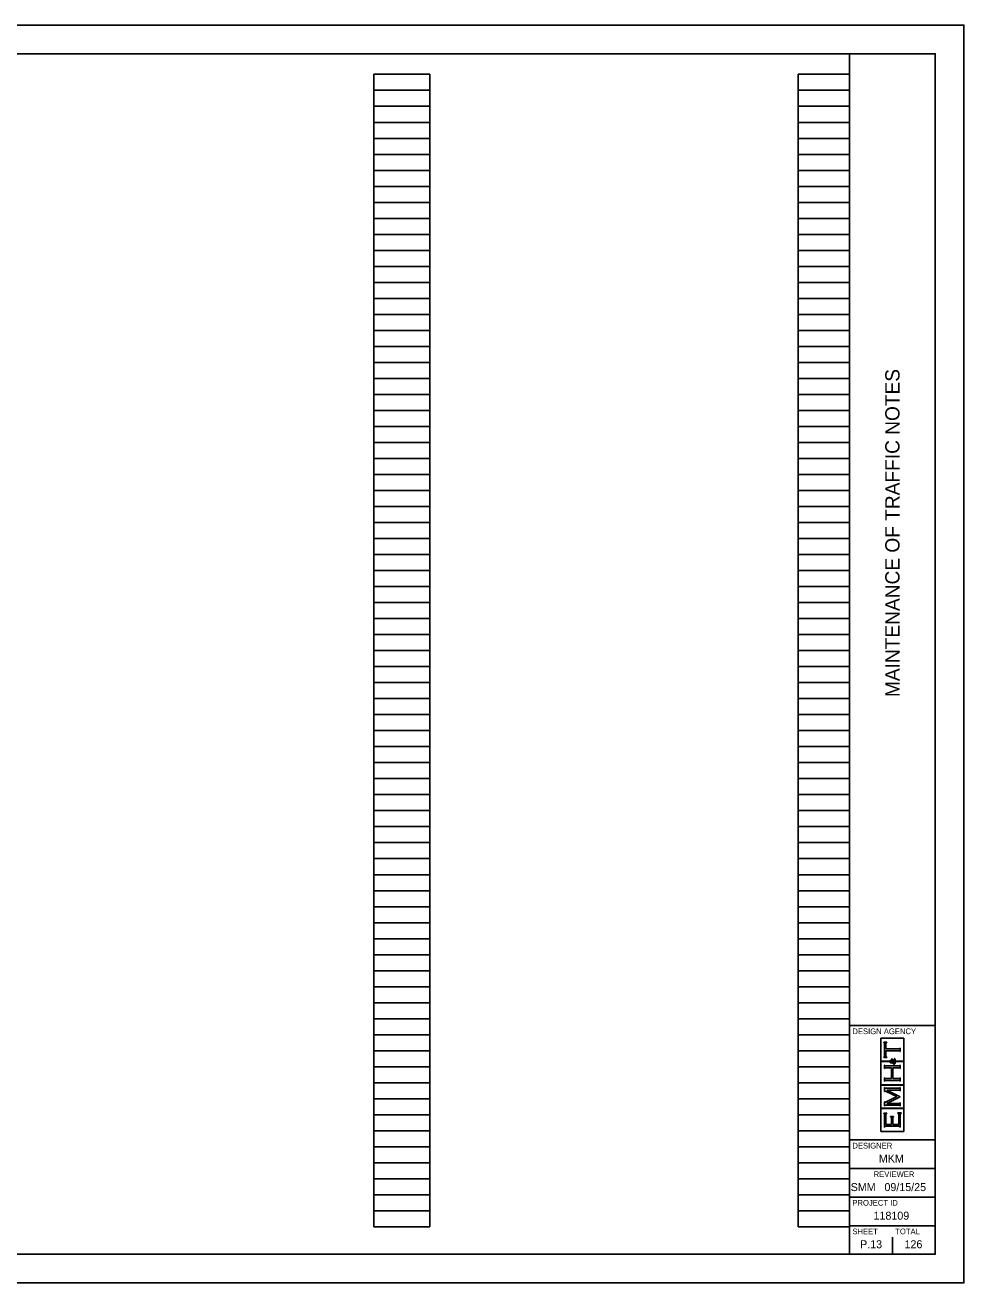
# Model space of a CAD drawing. Extents: x 0 to 34, y 0 to 22.
# Drawn here: x 17.58 to 34, y 0 to 22 of the extents above; entities that cross this region are included whole.
import ezdxf

# ---------------------------------------------------------------- set-up
doc = ezdxf.new("R2010")
doc.units = 0
for name, color, linetype in [('SH_Border', 7, 'Continuous'), ('SH_Cut_Line', 7, 'Continuous'), ('SH_Data', 7, 'Continuous')]:
    doc.layers.add(name, color=color, linetype=linetype)

msp = doc.modelspace()

# ---------------------------------------------------------------- linework, layer by layer
at = {"layer": 'SH_Border'}
for p, q in [((32, 0.5), (32, 21.5)), ((32, 4.5), (33.5, 4.5)), ((32, 2.5), (33.5, 2.5)), ((32, 2), (33.5, 2)), ((32, 1.5), (33.5, 1.5)), ((32, 1), (33.5, 1))]:
    msp.add_line(p, q, dxfattribs=at)
msp.add_lwpolyline([(1.5, 21.5), (33.5, 21.5), (33.5, 0.5), (1.5, 0.5)], close=True, dxfattribs=at)
at = {"layer": 'SH_Cut_Line'}
msp.add_lwpolyline([(0, 0), (34, 0), (34, 22), (0, 22)], close=True, dxfattribs=at)
at = {"layer": 'SH_Data'}
for p, q in [((23.68, 0.98), (23.68, 21.14)), ((23.68, 21.14), (24.66, 21.14)), ((24.66, 0.98), (24.66, 21.14)), ((31.1, 0.98), (31.1, 21.14)), ((31.1, 21.14), (32, 21.14)), ((32, 0.98), (32, 21.14)), ((23.68, 20.86), (24.66, 20.86)), ((31.1, 20.86), (32, 20.86)), ((23.68, 20.58), (24.66, 20.58)), ((31.1, 20.58), (32, 20.58)), ((23.68, 20.3), (24.66, 20.3)), ((31.1, 20.3), (32, 20.3)), ((23.68, 20.02), (24.66, 20.02)), ((31.1, 20.02), (32, 20.02)), ((23.68, 19.74), (24.66, 19.74)), ((31.1, 19.74), (32, 19.74)), ((23.68, 19.46), (24.66, 19.46)), ((31.1, 19.46), (32, 19.46)), ((23.68, 19.18), (24.66, 19.18)), ((31.1, 19.18), (32, 19.18)), ((23.68, 18.9), (24.66, 18.9)), ((31.1, 18.9), (32, 18.9)), ((23.68, 18.62), (24.66, 18.62)), ((31.1, 18.62), (32, 18.62)), ((23.68, 18.34), (24.66, 18.34)), ((31.1, 18.34), (32, 18.34)), ((23.68, 18.06), (24.66, 18.06)), ((31.1, 18.06), (32, 18.06)), ((23.68, 17.78), (24.66, 17.78)), ((31.1, 17.78), (32, 17.78)), ((23.68, 17.5), (24.66, 17.5)), ((31.1, 17.5), (32, 17.5)), ((23.68, 17.22), (24.66, 17.22)), ((31.1, 17.22), (32, 17.22)), ((23.68, 16.94), (24.66, 16.94)), ((31.1, 16.94), (32, 16.94)), ((23.68, 16.66), (24.66, 16.66)), ((31.1, 16.66), (32, 16.66)), ((23.68, 16.38), (24.66, 16.38)), ((31.1, 16.38), (32, 16.38)), ((23.68, 16.1), (24.66, 16.1)), ((31.1, 16.1), (32, 16.1)), ((23.68, 15.82), (24.66, 15.82)), ((31.1, 15.82), (32, 15.82)), ((23.68, 15.54), (24.66, 15.54)), ((31.1, 15.54), (32, 15.54)), ((23.68, 15.26), (24.66, 15.26)), ((31.1, 15.26), (32, 15.26)), ((23.68, 14.98), (24.66, 14.98)), ((31.1, 14.98), (32, 14.98)), ((23.68, 14.7), (24.66, 14.7)), ((31.1, 14.7), (32, 14.7)), ((23.68, 14.42), (24.66, 14.42)), ((31.1, 14.42), (32, 14.42)), ((23.68, 14.14), (24.66, 14.14)), ((31.1, 14.14), (32, 14.14)), ((23.68, 13.86), (24.66, 13.86)), ((31.1, 13.86), (32, 13.86)), ((23.68, 13.58), (24.66, 13.58)), ((31.1, 13.58), (32, 13.58)), ((23.68, 13.3), (24.66, 13.3)), ((31.1, 13.3), (32, 13.3)), ((23.68, 13.02), (24.66, 13.02)), ((31.1, 13.02), (32, 13.02)), ((23.68, 12.74), (24.66, 12.74)), ((31.1, 12.74), (32, 12.74)), ((23.68, 12.46), (24.66, 12.46)), ((31.1, 12.46), (32, 12.46)), ((23.68, 12.18), (24.66, 12.18)), ((31.1, 12.18), (32, 12.18)), ((23.68, 11.9), (24.66, 11.9)), ((31.1, 11.9), (32, 11.9)), ((23.68, 11.62), (24.66, 11.62)), ((31.1, 11.62), (32, 11.62)), ((23.68, 11.34), (24.66, 11.34)), ((31.1, 11.34), (32, 11.34)), ((23.68, 11.06), (24.66, 11.06)), ((31.1, 11.06), (32, 11.06)), ((23.68, 10.78), (24.66, 10.78)), ((31.1, 10.78), (32, 10.78)), ((23.68, 10.5), (24.66, 10.5)), ((31.1, 10.5), (32, 10.5)), ((23.68, 10.22), (24.66, 10.22)), ((31.1, 10.22), (32, 10.22)), ((23.68, 9.94), (24.66, 9.94)), ((31.1, 9.94), (32, 9.94)), ((23.68, 9.66), (24.66, 9.66)), ((31.1, 9.66), (32, 9.66)), ((23.68, 9.38), (24.66, 9.38)), ((31.1, 9.38), (32, 9.38)), ((23.68, 9.1), (24.66, 9.1)), ((31.1, 9.1), (32, 9.1)), ((23.68, 8.82), (24.66, 8.82)), ((31.1, 8.82), (32, 8.82)), ((23.68, 8.54), (24.66, 8.54)), ((31.1, 8.54), (32, 8.54)), ((23.68, 8.26), (24.66, 8.26)), ((31.1, 8.26), (32, 8.26)), ((23.68, 7.98), (24.66, 7.98)), ((31.1, 7.98), (32, 7.98)), ((23.68, 7.7), (24.66, 7.7)), ((31.1, 7.7), (32, 7.7)), ((23.68, 7.42), (24.66, 7.42)), ((31.1, 7.42), (32, 7.42)), ((23.68, 7.14), (24.66, 7.14)), ((31.1, 7.14), (32, 7.14)), ((23.68, 6.86), (24.66, 6.86)), ((31.1, 6.86), (32, 6.86)), ((23.68, 6.58), (24.66, 6.58)), ((31.1, 6.58), (32, 6.58)), ((23.68, 6.3), (24.66, 6.3)), ((31.1, 6.3), (32, 6.3)), ((23.68, 6.02), (24.66, 6.02)), ((31.1, 6.02), (32, 6.02)), ((23.68, 5.74), (24.66, 5.74)), ((31.1, 5.74), (32, 5.74)), ((23.68, 5.46), (24.66, 5.46)), ((31.1, 5.46), (32, 5.46)), ((23.68, 5.18), (24.66, 5.18)), ((31.1, 5.18), (32, 5.18)), ((23.68, 4.9), (24.66, 4.9)), ((31.1, 4.9), (32, 4.9)), ((23.68, 4.62), (24.66, 4.62)), ((31.1, 4.62), (32, 4.62)), ((23.68, 4.34), (24.66, 4.34)), ((31.1, 4.34), (32, 4.34)), ((32.952, 4.279), (32.547, 4.279)), ((32.547, 4.279), (32.547, 3.875)), ((32.598, 4.204), (32.598, 4.211)), ((32.598, 4.211), (32.65, 4.211)), ((32.603, 4.203), (32.598, 4.204)), ((32.606, 4.201), (32.603, 4.203)), ((32.608, 4.199), (32.606, 4.201)), ((32.61, 4.196), (32.608, 4.199)), ((32.611, 4.192), (32.61, 4.196)), ((32.611, 4.187), (32.611, 4.192)), ((32.611, 3.968), (32.611, 4.187)), ((32.638, 4.196), (32.637, 4.192)), ((32.637, 4.192), (32.637, 4.187)), ((32.637, 4.187), (32.637, 4.093)), ((32.64, 4.199), (32.638, 4.196)), ((32.642, 4.201), (32.64, 4.199)), ((32.645, 4.203), (32.642, 4.201)), ((32.65, 4.204), (32.645, 4.203)), ((32.65, 4.211), (32.65, 4.204)), ((32.952, 3.875), (32.952, 4.279)), ((23.68, 4.06), (24.66, 4.06)), ((31.1, 4.06), (32, 4.06)), ((32.61, 3.958), (32.611, 3.962)), ((32.611, 3.962), (32.611, 3.968)), ((32.637, 4.093), (32.864, 4.093)), ((32.864, 4.061), (32.637, 4.061)), ((32.637, 4.061), (32.637, 3.968)), ((32.637, 3.968), (32.637, 3.962)), ((32.637, 3.962), (32.638, 3.958)), ((32.864, 4.093), (32.869, 4.093)), ((32.87, 4.061), (32.864, 4.061)), ((32.869, 4.093), (32.873, 4.094)), ((32.874, 4.06), (32.87, 4.061)), ((32.873, 4.094), (32.876, 4.096)), ((32.876, 4.059), (32.874, 4.06)), ((32.876, 4.096), (32.878, 4.097)), ((32.878, 4.057), (32.876, 4.059)), ((32.878, 4.097), (32.88, 4.101)), ((32.88, 4.053), (32.878, 4.057)), ((32.88, 4.101), (32.881, 4.106)), ((32.881, 4.048), (32.88, 4.053)), ((32.881, 4.106), (32.888, 4.106)), ((32.888, 4.048), (32.881, 4.048)), ((32.888, 4.106), (32.888, 4.048)), ((23.68, 3.78), (24.66, 3.78)), ((31.1, 3.78), (32, 3.78)), ((32.547, 3.875), (32.696, 3.875)), ((32.696, 3.869), (32.547, 3.869)), ((32.547, 3.869), (32.547, 3.465)), ((32.598, 3.95), (32.603, 3.951)), ((32.598, 3.944), (32.598, 3.95)), ((32.65, 3.944), (32.598, 3.944)), ((32.603, 3.951), (32.606, 3.953)), ((32.606, 3.953), (32.608, 3.955)), ((32.608, 3.955), (32.61, 3.958)), ((32.611, 3.749), (32.611, 3.807)), ((32.611, 3.807), (32.617, 3.807)), ((32.617, 3.749), (32.611, 3.749)), ((32.617, 3.807), (32.619, 3.802)), ((32.618, 3.754), (32.617, 3.749)), ((32.62, 3.758), (32.618, 3.754)), ((32.619, 3.802), (32.62, 3.798)), ((32.62, 3.798), (32.623, 3.797)), ((32.623, 3.76), (32.62, 3.758)), ((32.623, 3.797), (32.625, 3.795)), ((32.625, 3.761), (32.623, 3.76)), ((32.625, 3.795), (32.629, 3.794)), ((32.629, 3.762), (32.625, 3.761)), ((32.629, 3.794), (32.635, 3.794)), ((32.635, 3.762), (32.629, 3.762)), ((32.635, 3.794), (32.864, 3.794)), ((32.732, 3.762), (32.635, 3.762)), ((32.638, 3.958), (32.64, 3.955)), ((32.64, 3.955), (32.642, 3.953)), ((32.642, 3.953), (32.645, 3.951)), ((32.645, 3.951), (32.65, 3.95)), ((32.65, 3.95), (32.65, 3.944)), ((32.696, 3.875), (32.696, 3.869)), ((32.703, 3.879), (32.705, 3.883)), ((32.703, 3.873), (32.703, 3.879)), ((32.703, 3.868), (32.703, 3.873)), ((32.705, 3.863), (32.703, 3.868)), ((32.705, 3.883), (32.708, 3.887)), ((32.708, 3.858), (32.705, 3.863)), ((32.708, 3.887), (32.711, 3.89)), ((32.709, 3.879), (32.708, 3.876)), ((32.708, 3.876), (32.708, 3.873)), ((32.708, 3.873), (32.708, 3.869)), ((32.708, 3.869), (32.71, 3.866)), ((32.712, 3.853), (32.708, 3.858)), ((32.712, 3.881), (32.709, 3.879)), ((32.71, 3.866), (32.712, 3.864)), ((32.711, 3.89), (32.715, 3.892)), ((32.714, 3.883), (32.712, 3.881)), ((32.712, 3.864), (32.715, 3.862)), ((32.718, 3.85), (32.712, 3.853)), ((32.716, 3.884), (32.714, 3.883)), ((32.715, 3.892), (32.72, 3.892)), ((32.715, 3.862), (32.718, 3.861)), ((32.72, 3.884), (32.716, 3.884)), ((32.718, 3.861), (32.721, 3.861)), ((32.726, 3.85), (32.718, 3.85)), ((32.72, 3.892), (32.725, 3.892)), ((32.724, 3.884), (32.72, 3.884)), ((32.721, 3.861), (32.723, 3.861)), ((32.723, 3.861), (32.725, 3.862)), ((32.728, 3.882), (32.724, 3.884)), ((32.725, 3.892), (32.729, 3.89)), ((32.725, 3.862), (32.728, 3.862)), ((32.729, 3.85), (32.726, 3.85)), ((32.731, 3.88), (32.728, 3.882)), ((32.728, 3.862), (32.731, 3.863)), ((32.729, 3.89), (32.732, 3.887)), ((32.731, 3.85), (32.729, 3.85)), ((32.734, 3.877), (32.731, 3.88)), ((32.731, 3.863), (32.735, 3.865)), ((32.734, 3.851), (32.731, 3.85)), ((32.732, 3.887), (32.736, 3.883)), ((32.732, 3.572), (32.732, 3.762)), ((32.737, 3.872), (32.734, 3.877)), ((32.737, 3.852), (32.734, 3.851)), ((32.735, 3.865), (32.74, 3.867)), ((32.736, 3.883), (32.74, 3.878)), ((32.74, 3.867), (32.737, 3.872)), ((32.741, 3.853), (32.737, 3.852)), ((32.738, 3.893), (32.738, 3.922)), ((32.738, 3.922), (32.741, 3.922)), ((32.741, 3.893), (32.738, 3.893)), ((32.74, 3.878), (32.744, 3.869)), ((32.741, 3.922), (32.741, 3.918)), ((32.741, 3.918), (32.742, 3.915)), ((32.742, 3.896), (32.741, 3.895)), ((32.741, 3.895), (32.741, 3.893)), ((32.746, 3.855), (32.741, 3.853)), ((32.742, 3.915), (32.743, 3.913)), ((32.743, 3.897), (32.742, 3.896)), ((32.743, 3.913), (32.745, 3.911)), ((32.745, 3.899), (32.743, 3.897)), ((32.744, 3.869), (32.754, 3.875)), ((32.745, 3.911), (32.749, 3.908)), ((32.746, 3.899), (32.745, 3.899)), ((32.748, 3.899), (32.746, 3.899)), ((32.752, 3.844), (32.746, 3.855)), ((32.755, 3.899), (32.748, 3.899)), ((32.749, 3.908), (32.756, 3.904)), ((32.756, 3.86), (32.751, 3.857)), ((32.751, 3.857), (32.754, 3.852)), ((32.757, 3.837), (32.752, 3.844)), ((32.754, 3.875), (32.764, 3.881)), ((32.754, 3.852), (32.757, 3.848)), ((32.763, 3.895), (32.755, 3.899)), ((32.756, 3.904), (32.763, 3.9)), ((32.761, 3.863), (32.756, 3.86)), ((32.757, 3.848), (32.761, 3.845)), ((32.763, 3.833), (32.757, 3.837)), ((32.864, 3.762), (32.759, 3.762)), ((32.759, 3.762), (32.759, 3.572)), ((32.764, 3.865), (32.761, 3.863)), ((32.761, 3.845), (32.765, 3.843)), ((32.763, 3.9), (32.77, 3.896)), ((32.772, 3.887), (32.763, 3.895)), ((32.768, 3.829), (32.763, 3.833)), ((32.764, 3.881), (32.772, 3.887)), ((32.768, 3.867), (32.764, 3.865)), ((32.765, 3.843), (32.769, 3.841)), ((32.774, 3.872), (32.768, 3.867)), ((32.774, 3.827), (32.768, 3.829)), ((32.769, 3.841), (32.773, 3.841)), ((32.77, 3.896), (32.776, 3.891)), ((32.773, 3.841), (32.778, 3.841)), ((32.782, 3.878), (32.774, 3.872)), ((32.779, 3.827), (32.774, 3.827)), ((32.776, 3.891), (32.781, 3.895)), ((32.778, 3.841), (32.782, 3.843)), ((32.779, 3.923), (32.781, 3.926)), ((32.782, 3.922), (32.779, 3.923)), ((32.785, 3.827), (32.779, 3.827)), ((32.781, 3.926), (32.787, 3.924)), ((32.781, 3.895), (32.784, 3.898)), ((32.785, 3.921), (32.782, 3.922)), ((32.786, 3.873), (32.782, 3.878)), ((32.782, 3.843), (32.786, 3.846)), ((32.784, 3.898), (32.786, 3.901)), ((32.786, 3.919), (32.785, 3.921)), ((32.79, 3.829), (32.785, 3.827)), ((32.788, 3.917), (32.786, 3.919)), ((32.786, 3.901), (32.788, 3.904)), ((32.791, 3.886), (32.786, 3.881)), ((32.786, 3.881), (32.791, 3.876)), ((32.788, 3.869), (32.786, 3.873)), ((32.786, 3.846), (32.789, 3.849)), ((32.787, 3.924), (32.792, 3.921)), ((32.789, 3.914), (32.788, 3.917)), ((32.788, 3.904), (32.789, 3.908)), ((32.79, 3.867), (32.788, 3.869)), ((32.789, 3.911), (32.789, 3.914)), ((32.789, 3.908), (32.789, 3.911)), ((32.789, 3.849), (32.791, 3.853)), ((32.791, 3.864), (32.79, 3.867)), ((32.793, 3.834), (32.79, 3.829)), ((32.794, 3.89), (32.791, 3.886)), ((32.791, 3.876), (32.795, 3.87)), ((32.791, 3.861), (32.791, 3.864)), ((32.791, 3.859), (32.791, 3.861)), ((32.791, 3.853), (32.791, 3.859)), ((32.792, 3.921), (32.795, 3.918)), ((32.797, 3.838), (32.793, 3.834)), ((32.796, 3.894), (32.794, 3.89)), ((32.795, 3.918), (32.798, 3.914)), ((32.795, 3.87), (32.797, 3.866)), ((32.798, 3.897), (32.796, 3.894)), ((32.797, 3.866), (32.798, 3.861)), ((32.799, 3.844), (32.797, 3.838)), ((32.798, 3.914), (32.799, 3.91)), ((32.799, 3.901), (32.798, 3.897)), ((32.798, 3.861), (32.799, 3.857)), ((32.799, 3.91), (32.799, 3.905)), ((32.799, 3.905), (32.799, 3.901)), ((32.803, 3.869), (32.799, 3.875)), ((32.799, 3.875), (32.952, 3.875)), ((32.799, 3.857), (32.799, 3.852)), ((32.799, 3.852), (32.799, 3.844)), ((32.952, 3.869), (32.803, 3.869)), ((32.864, 3.794), (32.869, 3.794)), ((32.87, 3.762), (32.864, 3.762)), ((32.869, 3.794), (32.873, 3.795)), ((32.874, 3.761), (32.87, 3.762)), ((32.873, 3.795), (32.876, 3.797)), ((32.876, 3.76), (32.874, 3.761)), ((32.876, 3.797), (32.878, 3.798)), ((32.878, 3.758), (32.876, 3.76)), ((32.878, 3.798), (32.88, 3.802)), ((32.88, 3.754), (32.878, 3.758)), ((32.88, 3.802), (32.881, 3.807)), ((32.881, 3.749), (32.88, 3.754)), ((32.881, 3.807), (32.888, 3.807)), ((32.888, 3.749), (32.881, 3.749)), ((32.888, 3.807), (32.888, 3.749)), ((32.952, 3.465), (32.952, 3.869)), ((32.611, 3.527), (32.611, 3.585)), ((32.611, 3.585), (32.617, 3.585)), ((32.617, 3.527), (32.611, 3.527)), ((32.617, 3.585), (32.619, 3.58)), ((32.618, 3.532), (32.617, 3.527)), ((32.62, 3.536), (32.618, 3.532)), ((32.619, 3.58), (32.62, 3.576)), ((32.62, 3.576), (32.623, 3.574)), ((32.623, 3.537), (32.62, 3.536)), ((32.623, 3.574), (32.625, 3.573)), ((32.625, 3.539), (32.623, 3.537)), ((32.625, 3.573), (32.629, 3.572)), ((32.629, 3.54), (32.625, 3.539)), ((32.629, 3.572), (32.635, 3.572)), ((32.635, 3.54), (32.629, 3.54)), ((32.635, 3.572), (32.732, 3.572)), ((32.864, 3.54), (32.635, 3.54)), ((32.759, 3.572), (32.864, 3.572)), ((32.864, 3.572), (32.87, 3.572)), ((32.87, 3.54), (32.864, 3.54)), ((32.87, 3.572), (32.874, 3.573)), ((32.874, 3.539), (32.87, 3.54)), ((32.874, 3.573), (32.876, 3.574)), ((32.876, 3.538), (32.874, 3.539)), ((32.876, 3.574), (32.878, 3.576)), ((32.878, 3.536), (32.876, 3.538)), ((32.878, 3.576), (32.88, 3.58)), ((32.88, 3.532), (32.878, 3.536)), ((32.88, 3.58), (32.881, 3.585)), ((32.881, 3.527), (32.88, 3.532)), ((32.881, 3.585), (32.888, 3.585)), ((32.888, 3.527), (32.881, 3.527)), ((32.888, 3.585), (32.888, 3.527)), ((23.68, 3.5), (24.66, 3.5)), ((31.1, 3.5), (32, 3.5)), ((32.547, 3.465), (32.952, 3.465)), ((32.952, 3.459), (32.547, 3.459)), ((32.547, 3.459), (32.547, 3.055)), ((32.611, 3.345), (32.611, 3.418)), ((32.611, 3.418), (32.617, 3.418)), ((32.617, 3.345), (32.611, 3.345)), ((32.617, 3.418), (32.619, 3.412)), ((32.62, 3.352), (32.617, 3.345)), ((32.619, 3.412), (32.62, 3.409)), ((32.62, 3.409), (32.623, 3.407)), ((32.622, 3.355), (32.62, 3.352)), ((32.626, 3.355), (32.622, 3.355)), ((32.623, 3.407), (32.625, 3.405)), ((32.625, 3.405), (32.629, 3.405)), ((32.629, 3.355), (32.626, 3.355)), ((32.629, 3.405), (32.635, 3.405)), ((32.633, 3.353), (32.629, 3.355)), ((32.64, 3.35), (32.633, 3.353)), ((32.635, 3.405), (32.864, 3.405)), ((32.825, 3.257), (32.64, 3.35)), ((32.864, 3.373), (32.654, 3.373)), ((32.654, 3.373), (32.888, 3.255)), ((32.75, 3.5), (32.75, 3.5)), ((32.864, 3.405), (32.869, 3.405)), ((32.87, 3.373), (32.864, 3.373)), ((32.869, 3.405), (32.873, 3.405)), ((32.874, 3.372), (32.87, 3.373)), ((32.873, 3.405), (32.876, 3.407)), ((32.876, 3.37), (32.874, 3.372)), ((32.876, 3.407), (32.878, 3.409)), ((32.878, 3.369), (32.876, 3.37)), ((32.878, 3.409), (32.88, 3.412)), ((32.88, 3.365), (32.878, 3.369)), ((32.88, 3.412), (32.881, 3.418)), ((32.881, 3.36), (32.88, 3.365)), ((32.881, 3.418), (32.888, 3.418)), ((32.888, 3.36), (32.881, 3.36)), ((32.888, 3.418), (32.888, 3.36)), ((32.952, 3.055), (32.952, 3.459)), ((23.68, 3.22), (24.66, 3.22)), ((31.1, 3.22), (32, 3.22)), ((32.611, 3.096), (32.611, 3.168)), ((32.611, 3.168), (32.617, 3.168)), ((32.617, 3.096), (32.611, 3.096)), ((32.617, 3.168), (32.62, 3.162)), ((32.618, 3.102), (32.617, 3.096)), ((32.62, 3.105), (32.618, 3.102)), ((32.62, 3.162), (32.622, 3.158)), ((32.623, 3.107), (32.62, 3.105)), ((32.622, 3.158), (32.626, 3.158)), ((32.625, 3.109), (32.623, 3.107)), ((32.629, 3.109), (32.625, 3.109)), ((32.626, 3.158), (32.627, 3.158)), ((32.627, 3.158), (32.633, 3.161)), ((32.635, 3.109), (32.629, 3.109)), ((32.633, 3.161), (32.641, 3.165)), ((32.864, 3.109), (32.635, 3.109)), ((32.641, 3.165), (32.825, 3.257)), ((32.888, 3.255), (32.654, 3.138)), ((32.654, 3.138), (32.864, 3.138)), ((32.864, 3.138), (32.869, 3.138)), ((32.87, 3.109), (32.864, 3.109)), ((32.869, 3.138), (32.873, 3.139)), ((32.874, 3.109), (32.87, 3.109)), ((32.873, 3.139), (32.876, 3.141)), ((32.876, 3.107), (32.874, 3.109)), ((32.876, 3.141), (32.878, 3.143)), ((32.878, 3.105), (32.876, 3.107)), ((32.878, 3.143), (32.88, 3.146)), ((32.88, 3.102), (32.878, 3.105)), ((32.88, 3.146), (32.881, 3.151)), ((32.881, 3.096), (32.88, 3.102)), ((32.881, 3.151), (32.888, 3.151)), ((32.888, 3.096), (32.881, 3.096)), ((32.888, 3.151), (32.888, 3.096)), ((23.68, 2.94), (24.66, 2.94)), ((31.1, 2.94), (32, 2.94)), ((32.547, 3.055), (32.952, 3.055)), ((32.952, 3.049), (32.547, 3.049)), ((32.547, 3.049), (32.547, 2.645)), ((32.598, 2.962), (32.598, 2.969)), ((32.598, 2.969), (32.65, 2.969)), ((32.603, 2.961), (32.598, 2.962)), ((32.606, 2.959), (32.603, 2.961)), ((32.608, 2.957), (32.606, 2.959)), ((32.61, 2.955), (32.608, 2.957)), ((32.611, 2.951), (32.61, 2.955)), ((32.611, 2.945), (32.611, 2.951)), ((32.611, 2.725), (32.611, 2.945)), ((32.64, 2.957), (32.638, 2.955)), ((32.638, 2.955), (32.638, 2.951)), ((32.638, 2.951), (32.638, 2.945)), ((32.638, 2.945), (32.638, 2.77)), ((32.642, 2.959), (32.64, 2.957)), ((32.645, 2.961), (32.642, 2.959)), ((32.65, 2.962), (32.645, 2.961)), ((32.65, 2.969), (32.65, 2.962)), ((32.719, 2.902), (32.719, 2.908)), ((32.719, 2.908), (32.772, 2.908)), ((32.724, 2.901), (32.719, 2.902)), ((32.728, 2.899), (32.724, 2.901)), ((32.729, 2.896), (32.728, 2.899)), ((32.731, 2.894), (32.729, 2.896)), ((32.732, 2.89), (32.731, 2.894)), ((32.732, 2.884), (32.732, 2.89)), ((32.732, 2.77), (32.732, 2.884)), ((32.76, 2.894), (32.759, 2.89)), ((32.759, 2.89), (32.759, 2.884)), ((32.759, 2.884), (32.759, 2.77)), ((32.761, 2.896), (32.76, 2.894)), ((32.763, 2.899), (32.761, 2.896)), ((32.767, 2.901), (32.763, 2.899)), ((32.772, 2.902), (32.767, 2.901)), ((32.772, 2.908), (32.772, 2.902)), ((32.848, 2.965), (32.848, 2.972)), ((32.848, 2.972), (32.901, 2.972)), ((32.853, 2.964), (32.848, 2.965)), ((32.857, 2.962), (32.853, 2.964)), ((32.859, 2.96), (32.857, 2.962)), ((32.86, 2.958), (32.859, 2.96)), ((32.861, 2.953), (32.86, 2.958)), ((32.861, 2.948), (32.861, 2.953)), ((32.861, 2.77), (32.861, 2.948)), ((32.889, 2.957), (32.888, 2.953)), ((32.888, 2.953), (32.888, 2.948)), ((32.888, 2.948), (32.888, 2.725)), ((32.891, 2.96), (32.889, 2.957)), ((32.892, 2.962), (32.891, 2.96)), ((32.896, 2.964), (32.892, 2.962)), ((32.901, 2.965), (32.896, 2.964)), ((32.901, 2.972), (32.901, 2.965)), ((32.952, 2.645), (32.952, 3.049)), ((23.68, 2.66), (24.66, 2.66)), ((31.1, 2.66), (32, 2.66)), ((32.547, 2.645), (32.952, 2.645)), ((32.617, 2.725), (32.611, 2.725)), ((32.619, 2.73), (32.617, 2.725)), ((32.62, 2.734), (32.619, 2.73)), ((32.623, 2.735), (32.62, 2.734)), ((32.625, 2.737), (32.623, 2.735)), ((32.629, 2.738), (32.625, 2.737)), ((32.635, 2.738), (32.629, 2.738)), ((32.864, 2.738), (32.635, 2.738)), ((32.638, 2.77), (32.732, 2.77)), ((32.759, 2.77), (32.861, 2.77)), ((32.87, 2.738), (32.864, 2.738)), ((32.874, 2.737), (32.87, 2.738)), ((32.876, 2.735), (32.874, 2.737)), ((32.878, 2.734), (32.876, 2.735)), ((32.88, 2.73), (32.878, 2.734)), ((32.881, 2.725), (32.88, 2.73)), ((32.888, 2.725), (32.881, 2.725)), ((23.68, 2.38), (24.66, 2.38)), ((31.1, 2.38), (32, 2.38)), ((23.68, 2.1), (24.66, 2.1)), ((31.1, 2.1), (32, 2.1)), ((23.68, 1.82), (24.66, 1.82)), ((31.1, 1.82), (32, 1.82)), ((23.68, 1.54), (24.66, 1.54)), ((31.1, 1.54), (32, 1.54)), ((23.68, 1.26), (24.66, 1.26)), ((31.1, 1.26), (32, 1.26)), ((23.68, 0.98), (24.66, 0.98)), ((31.1, 0.98), (32, 0.98)), ((32.375, 0.675), (32.375, 0.675)), ((32.75, 0.5), (32.75, 0.8))]:
    msp.add_line(p, q, dxfattribs=at)

# ---------------------------------------------------------------- texts
msp.add_text('MAINTENANCE OF TRAFFIC NOTES', height=0.25, rotation=90, dxfattribs=at).set_placement((32.875, 10.247))
for s, height, p in [('DESIGN AGENCY', 0.1, (32.05, 4.35)), ('DESIGNER', 0.1, (32.05, 2.35)), ('MKM', 0.14, (32.513, 2.105)), ('REVIEWER', 0.1, (32.422, 1.85)), ('SMM', 0.14, (32.02, 1.605)), ('09/15/25', 0.14, (32.611, 1.605)), ('PROJECT ID', 0.1, (32.05, 1.35)), ('118109', 0.14, (32.42, 1.105)), ('SHEET', 0.1, (32.05, 0.85)), ('TOTAL', 0.1, (32.8, 0.85)), ('P.13', 0.14, (32.185, 0.605)), ('126', 0.14, (32.962, 0.605))]:
    msp.add_text(s, height=height, dxfattribs=at).set_placement(p)

doc.saveas('drawing.dxf')
